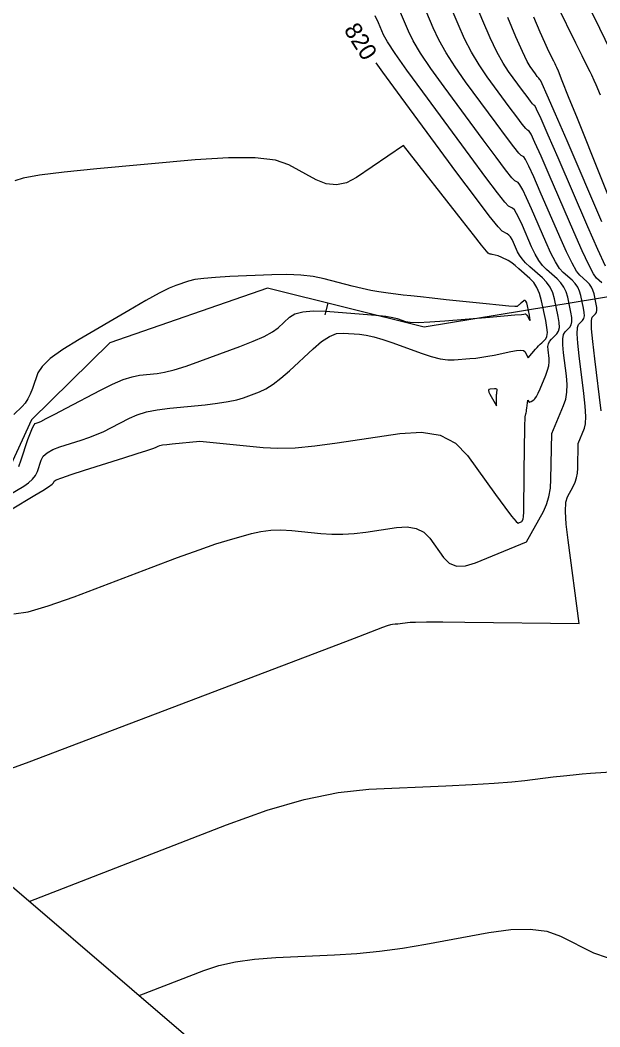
# Model space of a CAD drawing. Extents: x 1715724 to 1716561, y 394063 to 395906.
# Drawn here: x 1716184.2 to 1716231.8, y 394602.7 to 394685.4 of the extents above; entities that cross this region are included whole.
import ezdxf

# ---------------------------------------------------------------- set-up
doc = ezdxf.new("R2010")
doc.units = 0
for name, color, linetype in [('DT_X_Contour_Major', 7, 'Continuous'), ('DT_X_Contour_Minor', 7, 'Continuous'), ('DT_X_TIN_Hull', 7, 'Continuous'), ('GE_P_CL_10', 7, 'Continuous')]:
    doc.layers.add(name, color=color, linetype=linetype)

msp = doc.modelspace()

# ---------------------------------------------------------------- linework, layer by layer
at = {"layer": 'DT_X_Contour_Major'}
for points in [[(1716232.283, 394665.23), (1716231.667, 394666.596), (1716230.849, 394668.467), (1716228.4, 394674.133), (1716227.592, 394675.995), (1716227.004, 394677.33), (1716226.637, 394678.139), (1716226.49, 394678.421), (1716226.392, 394678.473), (1716226.307, 394678.562), (1716226.124, 394678.792), (1716225.844, 394679.161), (1716225.466, 394679.671), (1716224.328, 394681.216), (1716223.876, 394681.911), (1716223.373, 394682.838), (1716222.819, 394683.997), (1716222.214, 394685.387), (1716220.534, 394689.404)], [(1716183.385, 394645.212), (1716185.387, 394646.411), (1716186.047, 394646.811), (1716186.523, 394647.114), (1716186.817, 394647.319), (1716186.928, 394647.425), (1716186.979, 394647.58), (1716187.149, 394647.678), (1716187.618, 394647.859), (1716188.388, 394648.121), (1716189.458, 394648.465), (1716192.711, 394649.492), (1716193.788, 394649.835), (1716194.581, 394650.091), (1716195.089, 394650.262), (1716195.312, 394650.348), (1716195.527, 394650.461), (1716195.659, 394650.504), (1716195.893, 394650.549), (1716196.229, 394650.595), (1716196.667, 394650.642), (1716198.951, 394650.866), (1716204.149, 394650.345), (1716205.365, 394650.284), (1716206.784, 394650.325), (1716208.408, 394650.468), (1716210.235, 394650.713), (1716215.379, 394651.502), (1716217.174, 394651.61), (1716218.702, 394651.344), (1716219.963, 394650.703), (1716220.957, 394649.688), (1716223.251, 394646.48), (1716224.012, 394645.431), (1716224.575, 394644.689), (1716224.939, 394644.255), (1716225.105, 394644.129), (1716225.416, 394644.258), (1716225.519, 394644.443), (1716225.539, 394644.503), (1716225.554, 394644.605), (1716225.565, 394644.748), (1716225.571, 394644.933), (1716225.582, 394645.481), (1716225.587, 394645.788), (1716225.594, 394646.299), (1716225.603, 394647.014), (1716225.613, 394647.932), (1716225.643, 394650.654), (1716225.656, 394651.558), (1716225.67, 394652.228), (1716225.685, 394652.664), (1716225.703, 394652.867), (1716225.751, 394653.095), (1716225.77, 394653.188), (1716225.788, 394653.297), (1716225.808, 394653.42), (1716225.827, 394653.558), (1716225.92, 394654.237), (1716225.988, 394654.096), (1716226.011, 394654.075), (1716226.051, 394654.073), (1716226.108, 394654.089), (1716226.182, 394654.124), (1716226.402, 394654.242), (1716226.496, 394654.333), (1716226.613, 394654.517), (1716226.752, 394654.795), (1716226.915, 394655.167), (1716227.381, 394656.283), (1716227.529, 394656.683), (1716227.626, 394657.044), (1716227.67, 394657.368), (1716227.663, 394657.655), (1716227.574, 394658.368), (1716227.567, 394658.623), (1716227.61, 394658.853), (1716227.705, 394659.058), (1716227.85, 394659.238), (1716228.307, 394659.686), (1716228.442, 394659.9), (1716228.506, 394660.208), (1716228.498, 394660.608), (1716228.418, 394661.101), (1716228.11, 394662.54), (1716227.96, 394663.054), (1716227.743, 394663.517), (1716227.459, 394663.928), (1716227.108, 394664.288), (1716226.081, 394665.181), (1716225.729, 394665.509), (1716225.442, 394665.824), (1716225.221, 394666.126), (1716225.066, 394666.415), (1716224.74, 394667.17), (1716224.615, 394667.427), (1716224.483, 394667.633), (1716224.345, 394667.788), (1716224.201, 394667.891), (1716223.808, 394668.099), (1716223.465, 394668.458), (1716222.729, 394669.38), (1716221.602, 394670.866), (1716220.082, 394672.914), (1716215.507, 394679.128), (1716214.001, 394681.177), (1716213.449, 394681.934)]]:
    msp.add_lwpolyline(points, dxfattribs=at)
at = {"layer": 'DT_X_Contour_Minor'}
for points in [[(1716232.706, 394682.959), (1716231.82, 394684.758), (1716229.172, 394690.137)], [(1716231.996, 394663.862), (1716231.547, 394664.252), (1716231.305, 394664.599), (1716230.915, 394665.349), (1716230.378, 394666.502), (1716229.692, 394668.057), (1716227.668, 394672.74), (1716226.996, 394674.281), (1716226.5, 394675.39), (1716226.178, 394676.068), (1716226.032, 394676.315), (1716225.875, 394676.398), (1716225.738, 394676.541), (1716225.445, 394676.909), (1716224.995, 394677.502), (1716224.389, 394678.319), (1716222.564, 394680.798), (1716221.901, 394681.764), (1716221.281, 394682.803), (1716220.705, 394683.915), (1716220.173, 394685.1), (1716218.81, 394688.358)], [(1716231.939, 394653.339), (1716231.405, 394657.635), (1716231.242, 394659.057), (1716231.154, 394660.1), (1716231.141, 394660.765), (1716231.203, 394661.051), (1716231.466, 394661.31), (1716231.545, 394661.434), (1716231.581, 394661.611), (1716231.577, 394661.843), (1716231.531, 394662.127), (1716231.352, 394662.959), (1716231.266, 394663.256), (1716231.141, 394663.523), (1716230.977, 394663.761), (1716230.774, 394663.969), (1716230.181, 394664.484), (1716229.911, 394664.827), (1716229.547, 394665.468), (1716229.089, 394666.408), (1716228.536, 394667.646), (1716226.936, 394671.348), (1716226.401, 394672.568), (1716225.996, 394673.451), (1716225.72, 394673.998), (1716225.574, 394674.209), (1716225.359, 394674.323), (1716225.17, 394674.521), (1716224.766, 394675.027), (1716224.147, 394675.843), (1716223.312, 394676.968), (1716220.799, 394680.381), (1716219.926, 394681.617), (1716219.19, 394682.768), (1716218.592, 394683.834), (1716218.131, 394684.814), (1716217.086, 394687.312)], [(1716181.968, 394623.442), (1716184.932, 394624.532), (1716189.042, 394626.081), (1716205.696, 394632.406), (1716210.938, 394634.401), (1716212.012, 394634.813), (1716213.504, 394635.391), (1716214.003, 394635.582), (1716214.383, 394635.719), (1716214.643, 394635.802), (1716214.783, 394635.833), (1716214.998, 394635.842), (1716215.097, 394635.849), (1716215.233, 394635.862), (1716215.407, 394635.881), (1716215.619, 394635.906), (1716216.232, 394635.981), (1716216.686, 394636.003), (1716217.585, 394636.011), (1716218.931, 394636.006), (1716220.723, 394635.988), (1716230.127, 394635.871), (1716229.215, 394642.724), (1716229.066, 394644.049), (1716229.01, 394645.087), (1716229.047, 394645.836), (1716229.177, 394646.299), (1716229.647, 394647.148), (1716229.803, 394647.481), (1716229.916, 394647.842), (1716229.988, 394648.231), (1716230.018, 394648.649), (1716230.058, 394650.664), (1716230.579, 394651.915), (1716230.659, 394652.295), (1716230.675, 394652.898), (1716230.626, 394653.726), (1716230.514, 394654.777), (1716230.128, 394657.879), (1716230.017, 394658.912), (1716229.973, 394659.684), (1716229.996, 394660.196), (1716230.085, 394660.447), (1716230.413, 394660.769), (1716230.511, 394660.923), (1716230.556, 394661.143), (1716230.55, 394661.431), (1716230.493, 394661.785), (1716230.271, 394662.819), (1716230.164, 394663.188), (1716230.008, 394663.521), (1716229.804, 394663.816), (1716229.552, 394664.075), (1716228.814, 394664.716), (1716228.517, 394665.054), (1716228.179, 394665.586), (1716227.799, 394666.314), (1716227.379, 394667.236), (1716226.204, 394669.955), (1716225.806, 394670.854), (1716225.491, 394671.512), (1716225.262, 394671.928), (1716225.117, 394672.103), (1716224.842, 394672.248), (1716224.602, 394672.5), (1716224.087, 394673.145), (1716223.298, 394674.184), (1716222.236, 394675.617), (1716219.035, 394679.963), (1716217.951, 394681.47), (1716217.099, 394682.734), (1716216.478, 394683.752), (1716216.089, 394684.527), (1716215.362, 394686.266)], [(1716231.879, 394679.287), (1716231.538, 394680.117), (1716231.372, 394680.498), (1716231.165, 394680.915), (1716231.025, 394681.197), (1716230.763, 394681.729), (1716230.378, 394682.51), (1716229.87, 394683.542), (1716228.351, 394686.627)], [(1716183.658, 394636.672), (1716184.828, 394636.852), (1716186.48, 394637.32), (1716188.615, 394638.078), (1716194.954, 394640.485), (1716197.128, 394641.301), (1716198.895, 394641.944), (1716200.254, 394642.414), (1716201.207, 394642.711), (1716203.204, 394643.271), (1716203.972, 394643.444), (1716204.777, 394643.542), (1716205.619, 394643.564), (1716206.499, 394643.512), (1716208.894, 394643.272), (1716209.798, 394643.211), (1716210.715, 394643.209), (1716211.643, 394643.266), (1716212.584, 394643.382), (1716215.111, 394643.77), (1716215.992, 394643.823), (1716216.743, 394643.692), (1716217.362, 394643.377), (1716217.85, 394642.879), (1716218.976, 394641.303), (1716219.458, 394640.833), (1716220.059, 394640.603), (1716220.779, 394640.613), (1716221.618, 394640.864), (1716225.81, 394642.596), (1716227.19, 394645.086), (1716227.451, 394645.653), (1716227.642, 394646.286), (1716227.763, 394646.986), (1716227.814, 394647.751), (1716227.888, 394651.48), (1716228.853, 394653.794), (1716229.022, 394654.317), (1716229.118, 394654.895), (1716229.14, 394655.528), (1716229.088, 394656.216), (1716228.851, 394658.124), (1716228.792, 394658.767), (1716228.792, 394659.269), (1716228.85, 394659.627), (1716228.968, 394659.843), (1716229.36, 394660.227), (1716229.476, 394660.411), (1716229.531, 394660.675), (1716229.524, 394661.019), (1716229.456, 394661.443), (1716229.191, 394662.68), (1716229.062, 394663.121), (1716228.876, 394663.519), (1716228.632, 394663.872), (1716228.33, 394664.182), (1716227.447, 394664.948), (1716227.123, 394665.281), (1716226.81, 394665.705), (1716226.51, 394666.22), (1716226.223, 394666.826), (1716225.472, 394668.562), (1716225.21, 394669.14), (1716224.987, 394669.572), (1716224.803, 394669.858), (1716224.659, 394669.997), (1716224.325, 394670.173), (1716224.033, 394670.479), (1716223.408, 394671.263), (1716222.45, 394672.525), (1716221.159, 394674.266), (1716217.271, 394679.545), (1716215.976, 394681.324), (1716215.007, 394682.699), (1716214.365, 394683.671), (1716214.048, 394684.24), (1716213.638, 394685.22), (1716213.356, 394685.799)], [(1716232.005, 394668.877), (1716229.132, 394675.526), (1716228.187, 394677.708), (1716227.508, 394679.269), (1716227.095, 394680.209), (1716226.948, 394680.527), (1716226.909, 394680.548), (1716226.875, 394680.583), (1716226.803, 394680.674), (1716226.692, 394680.82), (1716226.542, 394681.022), (1716226.092, 394681.634), (1716225.85, 394682.058), (1716225.464, 394682.873), (1716224.932, 394684.078), (1716224.256, 394685.674)], [(1716233.823, 394667.758), (1716229.989, 394677.353), (1716229.267, 394679.157), (1716228.746, 394680.458), (1716228.425, 394681.254), (1716228.305, 394681.546), (1716228.252, 394681.653), (1716228.216, 394681.725), (1716228.149, 394681.861), (1716228.05, 394682.062), (1716227.92, 394682.326), (1716227.531, 394683.117), (1716227.309, 394683.601), (1716226.937, 394684.457), (1716226.414, 394685.688)], [(1716183.277, 394646.442), (1716184.471, 394647.157), (1716184.878, 394647.434), (1716185.201, 394647.73), (1716185.44, 394648.045), (1716185.597, 394648.378), (1716185.903, 394649.292), (1716186.085, 394649.617), (1716186.402, 394649.909), (1716186.854, 394650.166), (1716187.441, 394650.39), (1716189.186, 394650.941), (1716189.83, 394651.159), (1716190.453, 394651.401), (1716191.055, 394651.666), (1716191.636, 394651.955), (1716193.158, 394652.755), (1716193.794, 394653.032), (1716194.559, 394653.259), (1716195.454, 394653.439), (1716196.479, 394653.57), (1716199.386, 394653.855), (1716200.401, 394653.971), (1716201.267, 394654.106), (1716201.984, 394654.26), (1716202.551, 394654.432), (1716203.866, 394654.916), (1716204.389, 394655.16), (1716204.971, 394655.529), (1716205.612, 394656.023), (1716206.313, 394656.642), (1716208.262, 394658.458), (1716208.964, 394659.049), (1716209.608, 394659.46), (1716210.196, 394659.692), (1716210.726, 394659.744), (1716212.063, 394659.642), (1716212.611, 394659.569), (1716213.252, 394659.425), (1716213.986, 394659.213), (1716214.814, 394658.93), (1716217.144, 394658.083), (1716217.969, 394657.81), (1716218.696, 394657.626), (1716219.325, 394657.533), (1716219.856, 394657.528), (1716221.141, 394657.637), (1716221.628, 394657.686), (1716222.123, 394657.751), (1716222.626, 394657.833), (1716223.139, 394657.931), (1716224.516, 394658.216), (1716224.976, 394658.296), (1716225.321, 394658.322), (1716225.551, 394658.296), (1716225.667, 394658.216), (1716225.941, 394657.718), (1716226.541, 394658.404), (1716226.669, 394658.548), (1716226.797, 394658.686), (1716226.925, 394658.819), (1716227.052, 394658.947), (1716227.391, 394659.279), (1716227.485, 394659.464), (1716227.515, 394659.773), (1716227.48, 394660.205), (1716227.381, 394660.759), (1716227.029, 394662.4), (1716226.871, 394662.976), (1716226.661, 394663.472), (1716226.398, 394663.887), (1716226.084, 394664.223), (1716225.177, 394665.011), (1716224.866, 394665.276), (1716224.613, 394665.48), (1716224.418, 394665.624), (1716224.282, 394665.706), (1716223.781, 394665.948), (1716223.479, 394666.094), (1716222.982, 394666.191), (1716222.886, 394666.211), (1716222.811, 394666.229), (1716222.756, 394666.244), (1716222.722, 394666.257), (1716222.661, 394666.29), (1716222.51, 394666.467), (1716222.106, 394666.972), (1716221.447, 394667.805), (1716220.534, 394668.967), (1716215.681, 394675.155), (1716211.829, 394672.521), (1716211.002, 394672.086), (1716210.172, 394671.908), (1716209.339, 394671.988), (1716208.504, 394672.325), (1716206.274, 394673.569), (1716205.164, 394673.943), (1716203.507, 394674.132), (1716201.304, 394674.137), (1716198.554, 394673.957), (1716190.492, 394673.232), (1716187.803, 394672.966), (1716185.781, 394672.712), (1716184.428, 394672.471), (1716183.743, 394672.241)], [(1716184.064, 394648.771), (1716184.266, 394649.331), (1716184.826, 394651.004), (1716185.021, 394651.556), (1716185.186, 394651.959), (1716185.32, 394652.211), (1716185.424, 394652.314), (1716185.661, 394652.389), (1716185.871, 394652.483), (1716186.325, 394652.71), (1716187.021, 394653.07), (1716187.96, 394653.562), (1716190.789, 394655.05), (1716191.785, 394655.545), (1716192.65, 394655.914), (1716193.386, 394656.156), (1716193.991, 394656.272), (1716195.431, 394656.414), (1716196.057, 394656.516), (1716196.854, 394656.719), (1716197.823, 394657.021), (1716198.963, 394657.422), (1716202.231, 394658.626), (1716203.347, 394659.062), (1716204.244, 394659.466), (1716204.922, 394659.839), (1716205.38, 394660.181), (1716206.312, 394661.049), (1716206.762, 394661.323), (1716207.412, 394661.494), (1716208.262, 394661.561), (1716209.313, 394661.525), (1716212.381, 394661.291), (1716213.419, 394661.203), (1716214.232, 394661.114), (1716214.82, 394661.025), (1716215.182, 394660.934), (1716215.847, 394660.693), (1716216.237, 394660.628), (1716216.909, 394660.614), (1716217.863, 394660.653), (1716219.098, 394660.743), (1716222.767, 394661.052), (1716223.976, 394661.154), (1716224.849, 394661.229), (1716225.388, 394661.277), (1716225.593, 394661.299), (1716225.692, 394661.319), (1716225.731, 394661.312), (1716225.776, 394661.278), (1716225.827, 394661.214), (1716225.882, 394661.123), (1716226.038, 394660.84), (1716226.081, 394660.784), (1716226.096, 394660.825), (1716226.081, 394660.965), (1716226.038, 394661.202), (1716225.882, 394661.967), (1716225.821, 394662.21), (1716225.755, 394662.363), (1716225.682, 394662.428), (1716225.604, 394662.404), (1716225.388, 394662.22), (1716225.312, 394662.156), (1716225.246, 394662.101), (1716225.188, 394662.056), (1716225.14, 394662.019), (1716225.025, 394661.934), (1716224.834, 394661.923), (1716224.346, 394661.952), (1716223.561, 394662.021), (1716222.48, 394662.131), (1716219.201, 394662.478), (1716218.059, 394662.599), (1716217.09, 394662.704), (1716216.295, 394662.793), (1716215.674, 394662.864), (1716214.249, 394663.032), (1716213.675, 394663.115), (1716213.019, 394663.238), (1716212.283, 394663.401), (1716211.465, 394663.604), (1716209.177, 394664.198), (1716208.265, 394664.386), (1716207.243, 394664.505), (1716206.111, 394664.553), (1716204.871, 394664.531), (1716201.417, 394664.381), (1716200.234, 394664.315), (1716199.275, 394664.231), (1716198.541, 394664.127), (1716198.032, 394664.005), (1716196.974, 394663.655), (1716196.436, 394663.428), (1716195.614, 394663.011), (1716194.508, 394662.403), (1716193.119, 394661.605), (1716189.038, 394659.223), (1716187.677, 394658.381), (1716186.658, 394657.641), (1716185.978, 394657.003), (1716185.64, 394656.468), (1716185.191, 394655.177), (1716185.011, 394654.722), (1716184.809, 394654.327), (1716184.585, 394653.991), (1716184.339, 394653.715), (1716183.651, 394653.057)], [(1716223.404, 394655.04), (1716223.4, 394655.098), (1716223.359, 394655.137), (1716223.281, 394655.157), (1716223.167, 394655.158), (1716222.815, 394655.137), (1716222.713, 394655.104), (1716222.674, 394655.022), (1716222.697, 394654.891), (1716222.783, 394654.71), (1716223.326, 394653.751), (1716223.334, 394654.434), (1716223.337, 394654.571), (1716223.343, 394654.688), (1716223.353, 394654.784), (1716223.366, 394654.861), (1716223.404, 394655.04)], [(1716184.915, 394613.06), (1716201.137, 394619.352), (1716204.475, 394620.545), (1716207.537, 394621.429), (1716210.323, 394622.003), (1716212.833, 394622.267), (1716219.158, 394622.559), (1716221.343, 394622.669), (1716223.153, 394622.777), (1716224.59, 394622.885), (1716225.652, 394622.993), (1716227.985, 394623.279), (1716228.834, 394623.378), (1716229.63, 394623.461), (1716230.373, 394623.529), (1716231.063, 394623.581), (1716239.115, 394624.111)], [(1716193.955, 394605.323), (1716199.276, 394607.387), (1716200.501, 394607.784), (1716201.894, 394608.092), (1716203.456, 394608.31), (1716205.186, 394608.439), (1716210.024, 394608.662), (1716211.854, 394608.78), (1716213.714, 394608.967), (1716215.605, 394609.222), (1716217.527, 394609.546), (1716222.693, 394610.501), (1716224.515, 394610.751), (1716226.107, 394610.784), (1716227.47, 394610.6), (1716228.602, 394610.199), (1716231.316, 394608.842), (1716232.421, 394608.441)]]:
    msp.add_lwpolyline(points, dxfattribs=at)
at = {"layer": 'DT_X_TIN_Hull'}
msp.add_lwpolyline([(1716124.575, 394620.656), (1716148.932, 394620.106), (1716178.473, 394618.573), (1716198.368, 394601.547), (1716214.149, 394581.106), (1716226.914, 394558.689), (1716239.765, 394534.125), (1716253.999, 394509.733), (1716267.482, 394486.319), (1716281.648, 394460.466), (1716295.056, 394433.007), (1716310.248, 394404.289), (1716324.4, 394380.065), (1716338.753, 394353.428), (1716352.69, 394329.698), (1716364.178, 394305.34), (1716366.885, 394280.883)], dxfattribs=at)
at = {"layer": 'GE_P_CL_10'}
for p, q in [((1716306.2, 394674.833), (1716217.392, 394660.231)), ((1716204.525, 394663.424), (1716191.546, 394658.928)), ((1716217.392, 394660.231), (1716204.525, 394663.424)), ((1716209.465, 394662.198), (1716209.224, 394661.228)), ((1716191.546, 394658.928), (1716185.108, 394652.617)), ((1716185.108, 394652.617), (1716183.117, 394648.259))]:
    msp.add_line(p, q, dxfattribs=at)

# ---------------------------------------------------------------- texts
at = {"layer": 'DT_X_Contour_Major'}
msp.add_text('820', height=1.4, rotation=302.47326, dxfattribs=at).set_placement((1716210.747, 394684.646))

doc.saveas('drawing.dxf')
